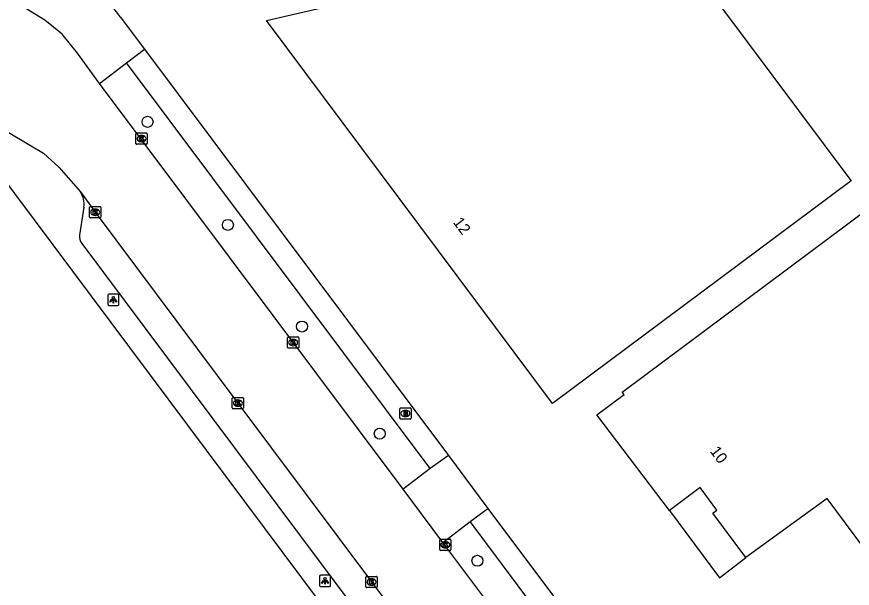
# Model space of a CAD drawing. Extents: x 156651 to 158072, y 387631 to 388990.
# Drawn here: x 157671.4 to 157745.5, y 388611.6 to 388662.3 of the extents above; entities that cross this region are included whole.
import ezdxf

# ---------------------------------------------------------------- set-up
doc = ezdxf.new("R2010")
doc.units = 0
for name, color, linetype in [('IMGEO_Boom', 7, 'Continuous'), ('IMGEO_Brandkraan', 7, 'Continuous'), ('IMGEO_Kolk', 7, 'Continuous'), ('IMGEO_Lichtpunt', 7, 'Continuous'), ('IMGEO_Pand', 7, 'Continuous'), ('IMGEO_Pand_nummerreeks', 7, 'Continuous'), ('IMGEO_Pand_overbouw', 7, 'Continuous'), ('IMGEO_Rijbaan_lokaal_gesloten', 7, 'Continuous'), ('IMGEO_Voetpad_open', 7, 'Continuous')]:
    doc.layers.add(name, color=color, linetype=linetype)

msp = doc.modelspace()

# ---------------------------------------------------------------- linework, layer by layer
at = {"layer": 'IMGEO_Boom'}
for centre in [(157683.008, 388652.998), (157690.137, 388643.849), (157696.715, 388634.823), (157703.613, 388625.307), (157712.281, 388614.019)]:
    msp.add_circle(centre, 0.489, dxfattribs=at)
at = {"layer": 'IMGEO_Brandkraan'}
for p, q in [((157705.389, 388626.671), (157705.389, 388627.523)), ((157705.464, 388627.597), (157706.316, 388627.597)), ((157705.877, 388627.377), (157705.902, 388627.377)), ((157706.39, 388627.523), (157706.39, 388626.671)), ((157706.316, 388626.597), (157705.464, 388626.597)), ((157705.9, 388626.817), (157705.875, 388626.817))]:
    msp.add_line(p, q, dxfattribs=at)
for points in [[(157705.389, 388626.671), (157705.389, 388627.523)], [(157705.464, 388627.597), (157706.316, 388627.597)], [(157705.737, 388627.297), (157705.737, 388626.897), (157705.95, 388626.897)], [(157705.968, 388627.297), (157705.737, 388627.297)], [(157705.916, 388627.216), (157705.862, 388627.216), (157705.862, 388627.14)], [(157705.862, 388627.14), (157705.915, 388627.14)], [(157705.924, 388627.064), (157705.862, 388627.064), (157705.862, 388626.983)], [(157705.862, 388626.983), (157705.924, 388626.983)], [(157706.39, 388627.523), (157706.39, 388626.671)], [(157706.316, 388626.597), (157705.464, 388626.597)]]:
    msp.add_lwpolyline(points, dxfattribs=at)
for centre, radius, start, end in [((157705.466, 388627.521), 0.0765, 91.55205, 178.44795), ((157705.466, 388627.521), 0.0765, 91.55205, 178.44795), ((157705.917, 388627.178), 0.0379, 267.82845, 90.93552), ((157705.925, 388627.023), 0.0404, 269.87594, 90.50774), ((157705.972, 388627.152), 0.145, 59.4692, 91.53667), ((157705.997, 388627.199), 0.0922, 285.51372, 58.15012), ((157706.002, 388627.007), 0.105, 301.31148, 78.98903), ((157706.314, 388627.521), 0.0765, 1.55205, 88.44795), ((157706.314, 388627.521), 0.0765, 1.55205, 88.44795), ((157705.466, 388626.673), 0.0765, 181.55205, 268.44795), ((157705.466, 388626.673), 0.0765, 181.55205, 268.44795), ((157705.956, 388627.148), 0.251, 268.66757, 293.53466), ((157706.314, 388626.673), 0.0765, 271.55205, 358.44795), ((157706.314, 388626.673), 0.0765, 271.55205, 358.44795)]:
    msp.add_arc(centre, radius, start, end, dxfattribs=at)
for centre, major_axis, ratio, start_param, end_param in [((157705.876, 388627.097), (-0.387, 0.002), 0.722429, 4.712389, 7.853982), ((157705.901, 388627.097), (-0.39, 0.002), 0.717154, 1.570796, 4.712389)]:
    msp.add_ellipse(centre, major_axis=major_axis, ratio=ratio, start_param=start_param, end_param=end_param, dxfattribs=at)
at = {"layer": 'IMGEO_Kolk'}
for p, q in [((157681.978, 388651.081), (157681.978, 388651.933)), ((157682.053, 388652.007), (157682.905, 388652.007)), ((157682.466, 388651.787), (157682.491, 388651.787)), ((157682.979, 388651.933), (157682.979, 388651.081)), ((157682.905, 388651.007), (157682.053, 388651.007)), ((157682.489, 388651.227), (157682.464, 388651.227)), ((157677.864, 388644.544), (157677.864, 388645.396)), ((157677.939, 388645.47), (157678.791, 388645.47)), ((157678.352, 388645.25), (157678.377, 388645.25)), ((157678.865, 388645.396), (157678.865, 388644.544)), ((157678.791, 388644.47), (157677.939, 388644.47)), ((157678.375, 388644.69), (157678.35, 388644.69)), ((157695.421, 388632.973), (157695.421, 388633.825)), ((157695.496, 388633.899), (157696.348, 388633.899)), ((157695.909, 388633.679), (157695.934, 388633.679)), ((157696.422, 388633.825), (157696.422, 388632.973)), ((157696.348, 388632.899), (157695.496, 388632.899)), ((157695.932, 388633.119), (157695.907, 388633.119)), ((157690.528, 388627.594), (157690.528, 388628.446)), ((157690.603, 388628.52), (157691.455, 388628.52)), ((157691.529, 388628.446), (157691.529, 388627.594)), ((157691.039, 388627.74), (157691.014, 388627.74)), ((157691.016, 388628.3), (157691.041, 388628.3)), ((157691.455, 388627.52), (157690.603, 388627.52)), ((157708.933, 388615.01), (157708.933, 388615.862)), ((157709.008, 388615.936), (157709.86, 388615.936)), ((157709.934, 388615.862), (157709.934, 388615.01)), ((157709.444, 388615.156), (157709.419, 388615.156)), ((157709.421, 388615.716), (157709.446, 388615.716)), ((157709.86, 388614.936), (157709.008, 388614.936)), ((157702.384, 388611.711), (157702.384, 388612.563)), ((157702.459, 388612.637), (157703.311, 388612.637)), ((157702.872, 388612.417), (157702.897, 388612.417)), ((157703.385, 388612.563), (157703.385, 388611.711)), ((157703.311, 388611.637), (157702.459, 388611.637)), ((157702.895, 388611.857), (157702.87, 388611.857))]:
    msp.add_line(p, q, dxfattribs=at)
for points in [[(157681.978, 388651.081), (157681.978, 388651.933)], [(157682.053, 388652.007), (157682.905, 388652.007)], [(157682.299, 388651.707), (157682.422, 388651.707), (157682.422, 388651.556), (157682.552, 388651.707), (157682.716, 388651.707), (157682.57, 388651.556), (157682.723, 388651.307), (157682.571, 388651.307), (157682.486, 388651.471), (157682.422, 388651.404), (157682.422, 388651.307), (157682.299, 388651.307), (157682.299, 388651.707)], [(157682.979, 388651.933), (157682.979, 388651.081)], [(157682.905, 388651.007), (157682.053, 388651.007)], [(157677.864, 388644.544), (157677.864, 388645.396)], [(157677.939, 388645.47), (157678.791, 388645.47)], [(157678.185, 388645.17), (157678.308, 388645.17), (157678.308, 388645.019), (157678.438, 388645.17), (157678.602, 388645.17), (157678.456, 388645.019), (157678.609, 388644.77), (157678.457, 388644.77), (157678.372, 388644.934), (157678.308, 388644.867), (157678.308, 388644.77), (157678.185, 388644.77), (157678.185, 388645.17)], [(157678.865, 388645.396), (157678.865, 388644.544)], [(157678.791, 388644.47), (157677.939, 388644.47)], [(157695.421, 388632.973), (157695.421, 388633.825)], [(157695.496, 388633.899), (157696.348, 388633.899)], [(157696.422, 388633.825), (157696.422, 388632.973)], [(157696.348, 388632.899), (157695.496, 388632.899)], [(157695.742, 388633.599), (157695.865, 388633.599), (157695.865, 388633.448), (157695.995, 388633.599), (157696.159, 388633.599), (157696.013, 388633.448), (157696.166, 388633.199), (157696.014, 388633.199), (157695.929, 388633.363), (157695.865, 388633.296), (157695.865, 388633.199), (157695.742, 388633.199), (157695.742, 388633.599)], [(157690.528, 388627.594), (157690.528, 388628.446)], [(157690.603, 388628.52), (157691.455, 388628.52)], [(157691.529, 388628.446), (157691.529, 388627.594)], [(157690.849, 388628.22), (157690.972, 388628.22), (157690.972, 388628.069), (157691.102, 388628.22), (157691.266, 388628.22), (157691.12, 388628.069), (157691.273, 388627.82), (157691.121, 388627.82), (157691.036, 388627.984), (157690.972, 388627.917), (157690.972, 388627.82), (157690.849, 388627.82), (157690.849, 388628.22)], [(157691.455, 388627.52), (157690.603, 388627.52)], [(157708.933, 388615.01), (157708.933, 388615.862)], [(157709.008, 388615.936), (157709.86, 388615.936)], [(157709.934, 388615.862), (157709.934, 388615.01)], [(157709.254, 388615.636), (157709.377, 388615.636), (157709.377, 388615.485), (157709.507, 388615.636), (157709.671, 388615.636), (157709.525, 388615.485), (157709.678, 388615.236), (157709.526, 388615.236), (157709.441, 388615.4), (157709.377, 388615.333), (157709.377, 388615.236), (157709.254, 388615.236), (157709.254, 388615.636)], [(157709.86, 388614.936), (157709.008, 388614.936)], [(157702.384, 388611.711), (157702.384, 388612.563)], [(157702.459, 388612.637), (157703.311, 388612.637)], [(157702.705, 388612.337), (157702.828, 388612.337), (157702.828, 388612.186), (157702.958, 388612.337), (157703.122, 388612.337), (157702.976, 388612.186), (157703.129, 388611.937), (157702.977, 388611.937), (157702.892, 388612.101), (157702.828, 388612.034), (157702.828, 388611.937), (157702.705, 388611.937), (157702.705, 388612.337)], [(157703.385, 388612.563), (157703.385, 388611.711)], [(157703.311, 388611.637), (157702.459, 388611.637)]]:
    msp.add_lwpolyline(points, dxfattribs=at)
for centre, start, end in [((157682.055, 388651.931), 91.55205, 178.44795), ((157682.055, 388651.931), 91.55205, 178.44795), ((157682.903, 388651.931), 1.55205, 88.44795), ((157682.903, 388651.931), 1.55205, 88.44795), ((157682.055, 388651.083), 181.55205, 268.44795), ((157682.055, 388651.083), 181.55205, 268.44795), ((157682.903, 388651.083), 271.55205, 358.44795), ((157682.903, 388651.083), 271.55205, 358.44795), ((157677.941, 388645.394), 91.55205, 178.44795), ((157677.941, 388645.394), 91.55205, 178.44795), ((157678.789, 388645.394), 1.55205, 88.44795), ((157678.789, 388645.394), 1.55205, 88.44795), ((157677.941, 388644.546), 181.55205, 268.44795), ((157677.941, 388644.546), 181.55205, 268.44795), ((157678.789, 388644.546), 271.55205, 358.44795), ((157678.789, 388644.546), 271.55205, 358.44795), ((157695.498, 388633.823), 91.55205, 178.44795), ((157695.498, 388633.823), 91.55205, 178.44795), ((157696.346, 388633.823), 1.55205, 88.44795), ((157696.346, 388633.823), 1.55205, 88.44795), ((157695.498, 388632.975), 181.55205, 268.44795), ((157695.498, 388632.975), 181.55205, 268.44795), ((157696.346, 388632.975), 271.55205, 358.44795), ((157696.346, 388632.975), 271.55205, 358.44795), ((157690.605, 388628.444), 91.55205, 178.44795), ((157690.605, 388628.444), 91.55205, 178.44795), ((157691.453, 388628.444), 1.55205, 88.44795), ((157691.453, 388628.444), 1.55205, 88.44795), ((157690.605, 388627.596), 181.55205, 268.44795), ((157690.605, 388627.596), 181.55205, 268.44795), ((157691.453, 388627.596), 271.55205, 358.44795), ((157691.453, 388627.596), 271.55205, 358.44795), ((157709.01, 388615.86), 91.55205, 178.44795), ((157709.01, 388615.86), 91.55205, 178.44795), ((157709.858, 388615.86), 1.55205, 88.44795), ((157709.858, 388615.86), 1.55205, 88.44795), ((157709.01, 388615.012), 181.55205, 268.44795), ((157709.01, 388615.012), 181.55205, 268.44795), ((157709.858, 388615.012), 271.55205, 358.44795), ((157709.858, 388615.012), 271.55205, 358.44795), ((157702.461, 388612.561), 91.55205, 178.44795), ((157702.461, 388612.561), 91.55205, 178.44795), ((157703.309, 388612.561), 1.55205, 88.44795), ((157703.309, 388612.561), 1.55205, 88.44795), ((157702.461, 388611.713), 181.55205, 268.44795), ((157702.461, 388611.713), 181.55205, 268.44795), ((157703.309, 388611.713), 271.55205, 358.44795), ((157703.309, 388611.713), 271.55205, 358.44795)]:
    msp.add_arc(centre, 0.0765, start, end, dxfattribs=at)
for centre, major_axis, ratio, start_param, end_param in [((157682.465, 388651.507), (-0.387, 0.002), 0.722429, 4.712389, 7.853982), ((157682.49, 388651.507), (-0.39, 0.002), 0.717154, 1.570796, 4.712389), ((157678.351, 388644.97), (-0.387, 0.002), 0.722429, 4.712389, 7.853982), ((157678.376, 388644.97), (-0.39, 0.002), 0.717154, 1.570796, 4.712389), ((157695.908, 388633.399), (-0.387, 0.002), 0.722429, 4.712389, 7.853982), ((157695.933, 388633.399), (-0.39, 0.002), 0.717154, 1.570796, 4.712389), ((157691.015, 388628.02), (-0.387, 0.002), 0.722429, 4.712389, 7.853982), ((157691.04, 388628.02), (-0.39, 0.002), 0.717154, 1.570796, 4.712389), ((157709.42, 388615.436), (-0.387, 0.002), 0.722429, 4.712389, 7.853982), ((157709.445, 388615.436), (-0.39, 0.002), 0.717154, 1.570796, 4.712389), ((157702.871, 388612.137), (-0.387, 0.002), 0.722429, 4.712389, 7.853982), ((157702.896, 388612.137), (-0.39, 0.002), 0.717154, 1.570796, 4.712389)]:
    msp.add_ellipse(centre, major_axis=major_axis, ratio=ratio, start_param=start_param, end_param=end_param, dxfattribs=at)
at = {"layer": 'IMGEO_Lichtpunt'}
for p, q in [((157679.477, 388637.604), (157679.477, 388636.797)), ((157679.477, 388637.604), (157679.477, 388636.797)), ((157680.379, 388637.699), (157679.571, 388637.699)), ((157680.379, 388637.699), (157679.571, 388637.699)), ((157680.473, 388636.797), (157680.473, 388637.604)), ((157680.473, 388636.797), (157680.473, 388637.604)), ((157679.571, 388636.703), (157680.379, 388636.703)), ((157679.571, 388636.703), (157680.379, 388636.703)), ((157698.26, 388612.638), (157698.26, 388611.831)), ((157698.26, 388612.638), (157698.26, 388611.831)), ((157699.162, 388612.733), (157698.354, 388612.733)), ((157699.162, 388612.733), (157698.354, 388612.733)), ((157699.256, 388611.831), (157699.256, 388612.638)), ((157699.256, 388611.831), (157699.256, 388612.638)), ((157698.354, 388611.737), (157699.162, 388611.737)), ((157698.354, 388611.737), (157699.162, 388611.737))]:
    msp.add_line(p, q, dxfattribs=at)
for points in [[(157679.851, 388637.268), (157679.89, 388637.24), (157679.702, 388636.978), (157679.664, 388637.005), (157679.851, 388637.268)], [(157679.953, 388637.22), (157680, 388637.22), (157680, 388636.898), (157679.953, 388636.898), (157679.953, 388637.22)], [(157680.063, 388637.24), (157680.101, 388637.267), (157680.288, 388637.005), (157680.249, 388636.977), (157680.063, 388637.24)], [(157698.634, 388612.302), (157698.673, 388612.274), (157698.485, 388612.012), (157698.447, 388612.039), (157698.634, 388612.302)], [(157698.736, 388612.254), (157698.783, 388612.254), (157698.783, 388611.932), (157698.736, 388611.932), (157698.736, 388612.254)], [(157698.846, 388612.274), (157698.884, 388612.301), (157699.071, 388612.039), (157699.032, 388612.011), (157698.846, 388612.274)]]:
    msp.add_lwpolyline(points, dxfattribs=at)
for centre in [(157679.976, 388637.402), (157698.759, 388612.436)]:
    msp.add_circle(centre, 0.0994, dxfattribs=at)
for centre, start, end in [((157679.571, 388637.604), 90, 180), ((157679.571, 388637.604), 90, 180), ((157680.379, 388637.604), 0, 90), ((157680.379, 388637.604), 0, 90), ((157679.571, 388636.797), 180, 270), ((157679.571, 388636.797), 180, 270), ((157680.379, 388636.797), 270, 0), ((157680.379, 388636.797), 270, 360), ((157698.354, 388612.638), 90, 180), ((157698.354, 388612.638), 90, 180), ((157699.162, 388612.638), 0, 90), ((157699.162, 388612.638), 0, 90), ((157698.354, 388611.831), 180, 270), ((157698.354, 388611.831), 180, 270), ((157699.162, 388611.831), 270, 0), ((157699.162, 388611.831), 270, 360)]:
    msp.add_arc(centre, 0.0946, start, end, dxfattribs=at)
at = {"layer": 'IMGEO_Pand'}
for points in [[(157718.936, 388627.974), (157693.551, 388661.992), (157693.957, 388662.086), (157728.767, 388670.129), (157731.675, 388666.23), (157745.341, 388647.91), (157745.453, 388647.76), (157718.936, 388627.974)], [(157746.56, 388615.176), (157743.319, 388619.558), (157736.103, 388614.301), (157733.166, 388618.244), (157733.533, 388618.517), (157732.039, 388620.517), (157729.33, 388618.494), (157722.887, 388626.992), (157725.299, 388628.798), (157725.13, 388629.007), (157752.601, 388649.52), (157759.292, 388654.516), (157765.131, 388646.696), (157764.75, 388646.411), (157772.861, 388635.524), (157773.253, 388635.817), (157773.588, 388635.369), (157766.899, 388630.371), (157746.56, 388615.176)]]:
    msp.add_lwpolyline(points, dxfattribs=at)
at = {"layer": 'IMGEO_Pand_overbouw'}
msp.add_lwpolyline([(157736.103, 388614.301), (157733.166, 388618.244), (157733.533, 388618.517), (157732.039, 388620.517), (157729.33, 388618.494), (157733.766, 388612.516)], close=True, dxfattribs=at)
at = {"layer": 'IMGEO_Rijbaan_lokaal_gesloten'}
for points in [[(157678.751, 388656.407), (157676.801, 388659.11), (157675.426, 388660.795), (157673.884, 388662.018), (157672.05, 388663.148)], [(157705.682, 388620.382), (157678.751, 388656.407)], [(157667.118, 388653.535), (157669.317, 388652.856), (157673.782, 388650.215), (157675.14, 388648.971), (157677.044, 388646.782)], [(157677.044, 388646.782), (157678.366, 388644.971), (157691.031, 388628.022), (157702.886, 388612.138), (157715.525, 388595.248), (157733.77, 388570.785), (157738.371, 388564.633)], [(157709.22, 388615.65), (157705.682, 388620.382)], [(157721.978, 388598.584), (157709.22, 388615.65)]]:
    msp.add_lwpolyline(points, dxfattribs=at)
at = {"layer": 'IMGEO_Voetpad_open'}
for points in [[(157680.574, 388662.334), (157682.743, 388659.448)], [(157681.139, 388658.244), (157682.743, 388659.448)], [(157682.743, 388659.448), (157709.701, 388623.366)], [(157678.751, 388656.407), (157681.139, 388658.244)], [(157708.09, 388622.205), (157681.139, 388658.244)], [(157720.519, 388580.603), (157669.545, 388648.866)], [(157677.367, 388645.418), (157676.972, 388642.94)], [(157677.167, 388642.199), (157704.197, 388606.033), (157722.201, 388581.906)], [(157709.701, 388623.366), (157708.09, 388622.205)], [(157709.701, 388623.366), (157713.197, 388618.671)], [(157708.09, 388622.205), (157705.682, 388620.382)], [(157711.646, 388617.502), (157713.197, 388618.671)], [(157713.197, 388618.671), (157726.014, 388601.557)], [(157709.22, 388615.65), (157711.646, 388617.502)], [(157724.428, 388600.374), (157711.646, 388617.502)]]:
    msp.add_lwpolyline(points, dxfattribs=at)
for centre, radius, start, end in [((157665.976, 388651.621), 18.107, 36.2731, 45.34606), ((157675.383, 388645.668), 1.999, 352.80302, 33.84185), ((157677.995, 388642.813), 1.031, 172.92112, 216.56601)]:
    msp.add_arc(centre, radius, start, end, dxfattribs=at)

# ---------------------------------------------------------------- texts
at = {"layer": 'IMGEO_Pand_nummerreeks'}
for s, rotation, p in [('12', 306.73113, (157710.065, 388644.076)), ('10', 306.76076, (157732.865, 388623.742))]:
    msp.add_text(s, height=1, rotation=rotation, dxfattribs=at).set_placement(p)

doc.saveas('drawing.dxf')
